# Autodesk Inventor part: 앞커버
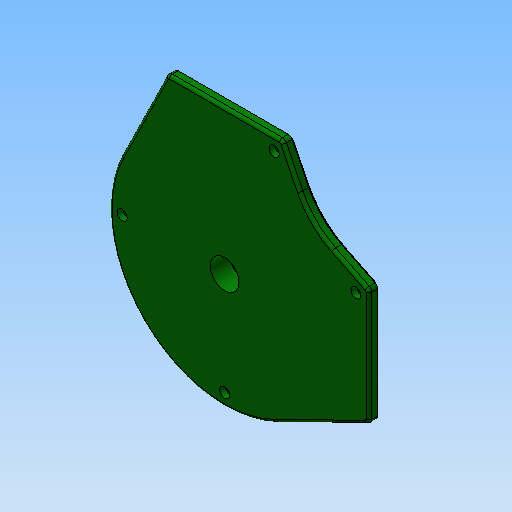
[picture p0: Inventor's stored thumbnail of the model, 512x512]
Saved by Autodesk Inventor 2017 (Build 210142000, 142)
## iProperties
Created: 2017-05
Part Number: 앞커버
Material: 알루미늄 6061
Document SubType Name: Modeling
Designer: mduedu
Density: 2.71 g/cm^3
Mass: 725.228 g
Surface Area: 595.074 cm^2
Volume: 267.612 cm^3
Appearance: 진녹색
Author: mduedu
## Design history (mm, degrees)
sketch "스케치1"
  geometry: L1 (-71.801, 35.28)-(-40, 100); L2 (-40, 100)-(40, 100); L3 (40, 100)-(52.248, 75.073); L4 (35.28, 71.801)-(59.768, 59.768); L5 (100, 40)-(100, -40); L6 (100, -40)-(35.28, -71.801); L7 (75.073, 52.248)-(100, 40); L8 (59.768, 59.768)-(71.801, 35.28); L9 (33.075, -67.313)-(95, -36.886); L10 (95, -36.886)-(95, 36.886); L11 (95, 36.886)-(72.868, 47.76); L12 (47.76, 72.868)-(36.886, 95); L13 (36.886, 95)-(-36.886, 95); L14 (-36.886, 95)-(-67.313, 33.075); A1 r 80 centre (0, 0) between (71.801, 35.28) and (-71.801, 35.28); A2 r 80 centre (0, 0) between (35.28, -71.801) and (71.801, 35.28); A3 r 80 centre (0, 0) between (-71.801, 35.28) and (35.28, -71.801); A4 r 50 centre (97.123, 97.123) between (52.248, 75.073) and (75.073, 52.248); A5 r 55 centre (97.123, 97.123) between (47.76, 72.868) and (72.868, 47.76); A6 r 75 centre (0, 0) between (-67.313, 33.075) and (33.075, -67.313); 3 further points
  constraints: 29 end point, 15 tangent, 14 point on circle, 6 centre point, 2 midpoint, 2 perpendicular, 2 point on line, 1 coincident, 1 horizontal, 1 horizontal alignment, 1 vertical alignment, 6 other
  dimensions: "d0" = 160 diameter of A1; "d1" = 100 distance from line of L2 point (0, 0); "d2" = 100 distance from line of L5 point (0, 0); "d3" = 80 distance of L1.end L2.end; "d4" = 80 distance of L5.start L5.end; "d5" = 50 radius of A4; "d6" = 5 distance between parallel lines of L13 L2
extrude "돌출1" new body sketch "스케치1" distance "d7" = 5; taper "d8" = 0 deg
fillet "모깎기1" dims "d9" = 3
sketch "스케치2"
  geometry: C1 r 22 at (0, 0); 1 further point
  constraints: 1 centre point, 1 coincident
  dimensions: "d10" = 44 diameter of C1
extrude "돌출2" join sketch "스케치2" distance "d11" = 12.5; taper "d12" = 0 deg
sketch "스케치3"
  geometry: C1 r 18.5 at (0, 0); 1 further point
  constraints: 1 centre point, 1 coincident
  dimensions: "d13" = 37 diameter of C1
extrude "돌출3" cut sketch "스케치3" distance "d14" = 9; taper "d15" = 0 deg
sketch "스케치5"
  geometry: L1 (-67.313, 33.075)-(-37.71, 93.323) reference; L2 (-35.017, 95)-(35.017, 95) reference; L3 (37.71, 93.323)-(47.76, 72.868) reference; L4 (72.868, 47.76)-(93.323, 37.71) reference; L5 (95, 35.017)-(95, -35.017) reference; L6 (93.323, -37.71)-(33.075, -67.313) reference; L7 (93.323, 37.71)-(72.868, 47.76) reference; L8 (95, -35.017)-(95, 35.017) reference; L9 (35.017, 95)-(-35.017, 95) reference; L10 (47.76, 72.868)-(37.71, 93.323) reference; C1 r 4 at (-71, 0); C2 r 4 at (0, -71); C3 r 4 at (91, 34.394); C4 r 4 at (34.394, 91); A1 r 75 centre (0, 0) between (-67.313, 33.075) and (33.075, -67.313) reference; A2 r 3 centre (-35.017, 92) between (-35.017, 95) and (-37.71, 93.323) reference; A3 r 3 centre (35.017, 92) between (37.71, 93.323) and (35.017, 95) reference; A4 r 55 centre (97.123, 97.123) between (47.76, 72.868) and (72.868, 47.76) reference; A5 r 3 centre (92, 35.017) between (95, 35.017) and (93.323, 37.71) reference; A6 r 3 centre (92, -35.017) between (93.323, -37.71) and (95, -35.017) reference; A7 r 75 centre (0, 0) between (-67.313, 33.075) and (33.075, -67.313) reference; 5 further points
  constraints: 6 tangent, 4 centre point, 4 coincident, 3 equal radius, 1 horizontal alignment, 1 vertical alignment
  dimensions: "d39" = 8 diameter of C1
  node "절단 모서리 투영1"
sketch "스케치7"
  geometry: L1 (100, -38.131)-(100, 38.131) reference; L2 (98.323, 40.824)-(75.073, 52.248) reference; L3 (52.248, 75.073)-(40.824, 98.323) reference; L4 (38.131, 100)-(-38.131, 100) reference; L5 (-40.824, 98.323)-(-71.801, 35.28) reference; L6 (35.28, -71.801)-(98.323, -40.824) reference; L7 (35.017, 96)-(-35.017, 96) reference; L8 (48.658, 73.309)-(38.607, 93.764) reference; L9 (93.764, 38.607)-(73.309, 48.658) reference; L10 (96, -35.017)-(96, 35.017) reference; L11 (33.516, -68.211)-(93.764, -38.607) reference; L12 (-38.607, 93.764)-(-68.211, 33.516) reference; A1 r 3 centre (97, -38.131) between (98.323, -40.824) and (100, -38.131) reference; A2 r 3 centre (97, 38.131) between (100, 38.131) and (98.323, 40.824) reference; A3 r 50 centre (97.123, 97.123) between (52.248, 75.073) and (75.073, 52.248) reference; A4 r 3 centre (38.131, 97) between (40.824, 98.323) and (38.131, 100) reference; A5 r 3 centre (-38.131, 97) between (-38.131, 100) and (-40.824, 98.323) reference; A6 r 80 centre (0, 0) between (-71.801, 35.28) and (35.28, -71.801) reference; A7 r 4 centre (35.017, 92) between (38.607, 93.764) and (35.017, 96) reference; A8 r 54 centre (97.123, 97.123) between (48.658, 73.309) and (73.309, 48.658) reference; A9 r 4 centre (92, 35.017) between (96, 35.017) and (93.764, 38.607) reference; A10 r 4 centre (92, -35.017) between (93.764, -38.607) and (96, -35.017) reference; A11 r 76 centre (0, 0) between (-68.211, 33.516) and (33.516, -68.211) reference; A12 r 4 centre (-35.017, 92) between (-35.017, 96) and (-38.607, 93.764) reference; 1 further point
extrude "돌출4" join sketch "스케치7" distance "d47" = 6; taper "d48" = 0 deg
sketch "스케치6"
  geometry: 4 further points
  constraints: 4 other
hole "구멍2" sketch "스케치6" at (0, -71), (91, 34.394), (34.394, 91), (-71, 0) diameter "d40" = 3.4; stored, may be unused: countersink angle "d44" = 90 deg, drill point angle "d46" = 0 deg; dims "d41" = 6, "d42" = 7, "d43" = 4, "d45" = 8
hole "구멍1" diameter "d18" = 20; stored, may be unused: countersink angle "d22" = 90 deg, drill point angle "d24" = 118 deg; dims "d19" = 6, "d20" = 4, "d21" = 2, "d23" = 8, "d50" = 10, "d51" = 10
fillet "모깎기2" dims "d25" = 3
chamfer "모따기1" distance "d27" = 1; stored, may be unused: second distance "d28" = 2, angle "d29" = 45 deg
chamfer "모따기2" distance "d33" = 1; stored, may be unused: second distance "d34" = 2, angle "d35" = 45 deg
chamfer "모따기3" distance "d36" = 1; stored, may be unused: second distance "d37" = 2, angle "d38" = 45 deg
fillet "모깎기3" dims "d49" = 2
node "솔리드1"
node "참조1"
